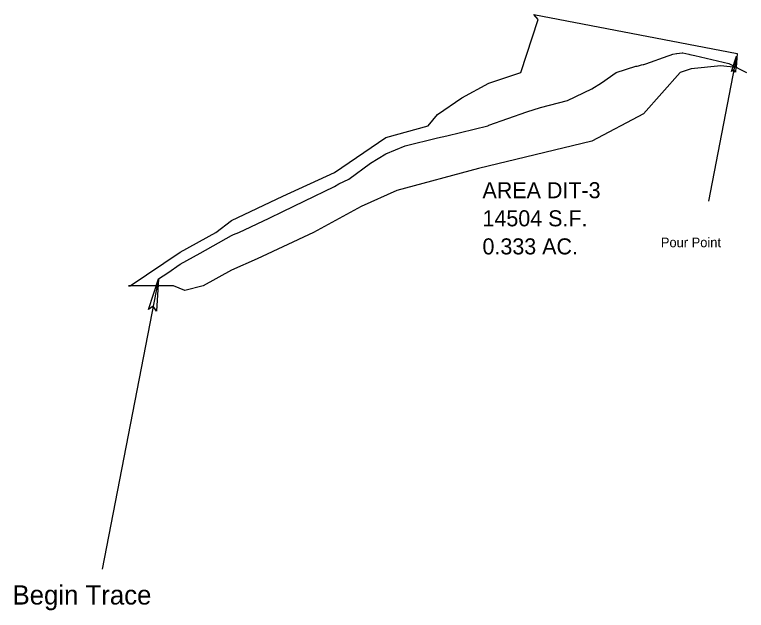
# Model space of a CAD drawing. Extents: x 3290 to 5445, y 2664 to 3371.
import ezdxf

# ---------------------------------------------------------------- set-up
doc = ezdxf.new("R2010")
doc.units = 0
for name, color, linetype in [('Default', 7, 'Continuous'), ('DESIGN - SCRATCH - User 1', 7, 'Continuous'), ('SURVEY - CENTERLINE - Preliminary', 7, 'Continuous'), ('SURVEY - CENTERLINE - Preliminary Text', 7, 'Continuous'), ('SURVEY - DRAINAGE - Area Shapes', 7, 'Continuous')]:
    doc.layers.add(name, color=color, linetype=linetype)

msp = doc.modelspace()

# ---------------------------------------------------------------- linework, layer by layer
at = {"layer": 'DESIGN - SCRATCH - User 1'}
msp.add_line((3739.54, 3009.01), (3722.01, 2918.57), dxfattribs=at)
msp.add_lwpolyline([(3739.54, 3009.01), (3738.86, 2998.91), (3737.88, 3000.42), (3736.35, 2999.4)], close=True, dxfattribs=at)
msp.add_lwpolyline([(3739.54, 3009.01), (3738.86, 2998.91), (3737.88, 3000.42), (3736.35, 2999.4), (3739.54, 3009.01)], dxfattribs=at)
at = {"layer": 'SURVEY - CENTERLINE - Preliminary'}
msp.add_lwpolyline([(3379.45, 2870.27), (3385.11, 2873.88), (3392.78, 2879.39), (3405.27, 2886.2), (3424.85, 2897.18), (3426.18, 2897.76), (3429.51, 2899.13), (3448.25, 2908.11), (3456.93, 2912.14), (3470.14, 2918.65), (3489.01, 2927.77), (3491.82, 2929.41), (3498, 2932.32), (3511.52, 2942.21), (3521.08, 2948.2), (3533, 2953.18), (3553.16, 2958.05), (3559.06, 2959.41), (3584.46, 2965.51), (3584.93, 2965.83), (3585.24, 2966), (3608.87, 2974.24), (3617.32, 2976.93), (3634.18, 2981.25), (3649.39, 2988.71), (3655.46, 2992.42), (3664.61, 2998.69), (3676.69, 3002.63), (3677.49, 3002.82), (3678.44, 3003.04), (3680.24, 3003.46), (3681.38, 3003.73), (3681.47, 3003.76), (3681.68, 3003.82), (3682.91, 3004.2), (3696.85, 3009.2), (3698.11, 3009.65), (3699.72, 3010.23), (3699.72, 3010.23), (3702.08, 3010.55), (3702.3, 3010.58), (3705.58, 3011.03), (3706.09, 3011.08), (3709.83, 3010.2), (3710.32, 3010.09), (3713.55, 3009.32), (3734.66, 3004.29), (3745.62, 2998.69)], dxfattribs=at)
at = {"layer": 'SURVEY - CENTERLINE - Preliminary Text'}
msp.add_line((3379.45, 2870.27), (3344.39, 2689.37), dxfattribs=at)
msp.add_lwpolyline([(3379.45, 2870.27), (3378.08, 2850.06), (3376.12, 2853.09), (3373.07, 2851.03)], close=True, dxfattribs=at)
msp.add_lwpolyline([(3379.45, 2870.27), (3378.08, 2850.06), (3376.12, 2853.09), (3373.07, 2851.03), (3379.45, 2870.27)], dxfattribs=at)
at = {"layer": 'SURVEY - DRAINAGE - Area Shapes'}
msp.add_line((3360.7, 2865.94), (3361.69, 2865.94), dxfattribs=at)
for points in [[(3613.18, 3034.84), (3739.81, 3010.61), (3739.26, 3001.94), (3729.7, 3002.97), (3711.24, 3001.08), (3704.31, 2998.69), (3681.47, 2972.96), (3649.39, 2955.98), (3578.76, 2939.02), (3527.95, 2925.21), (3505.56, 2915.19), (3475.9, 2899.13), (3440.83, 2882.6), (3424.85, 2875.6), (3407.31, 2865.94), (3395.69, 2862.93), (3388.83, 2865.94), (3360.7, 2865.94)], [(3361.69, 2865.94), (3392.78, 2886.73), (3415.12, 2899.13), (3424.85, 2906.59), (3456.93, 2921.74), (3489.01, 2936.48), (3521.08, 2958.29), (3547.33, 2965.51), (3553.16, 2972.59), (3568.32, 2983.01), (3585.24, 2992.22), (3605.12, 2998.69), (3615.98, 3031.88), (3613.18, 3034.84)]]:
    msp.add_lwpolyline(points, dxfattribs=at)

# ---------------------------------------------------------------- texts
at = {"layer": 'Default'}
for s, p in [('AREA DIT-3', (3581.23, 2920.43)), ('14504 S.F.', (3581.23, 2902.93)), ('0.333 AC.', (3581.23, 2885.43))]:
    msp.add_text(s, height=10, dxfattribs=at).set_placement(p)
at = {"layer": 'DESIGN - SCRATCH - User 1'}
msp.add_text('Pour Point', height=6, dxfattribs=at).set_placement((3692.35, 2889.9))
at = {"layer": 'SURVEY - CENTERLINE - Preliminary Text'}
msp.add_text('Begin Trace', height=12, dxfattribs=at).set_placement((3288.44, 2667.25))

doc.saveas('drawing.dxf')
